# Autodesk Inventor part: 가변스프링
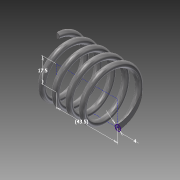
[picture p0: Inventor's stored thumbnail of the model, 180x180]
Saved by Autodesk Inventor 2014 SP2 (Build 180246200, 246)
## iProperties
Created: 2015-03
Part Number: 가변스프링
Material: 강철, 탄소
Document SubType Name: Modeling
Designer: 201-01
Density: 7.87 g/cm^3
Appearance: 반연마
Mass: 47.9796 g
Surface Area: 62.0291 cm^2
Volume: 6.09652 cm^3
Author: 201-01
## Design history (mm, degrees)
sketch "스케치2"
  geometry: L1 (0, 0)-(43.5, 0); L2 (43.5, 0)-(43.5, -17.5); L3 (43.5, -17.5)-(0, -17.5); L4 (0, -17.5)-(0, 0); C1 r 2 at (0, -17.5)
  constraints: 8 end point, 2 parallel, 1 centre point, 1 coincident, 1 horizontal, 1 perpendicular
  dimensions: "d0" = 17.5 distance of L1.end L2.end; "d1" = 43.5 distance of L2.end L3.end (derived); "d2" = 4 diameter of C1
feature "코일1" sketch "스케치2" pitch "d3" = 10; turns "d5" = 4.5; dims "d4" = 43.5 (= d1), "d6" = 0, angle "d7" = 90 deg, angle "d8" = 90 deg, "d9" = 0, "d10" = 0
sketch "스케치3"
  geometry: L1 (0, -19.5)-(0, -15.5) reference; 1 further point
  constraints: 1 vertical alignment
extrude "돌출1" cut sketch "스케치3" distance "d11" = 10; taper "d12" = 0 deg
node "작업 평면1"
sketch "스케치4"
  geometry: L1 (0, 15.5)-(0, 19.5) reference; 2 further points
  constraints: 2 other
extrude "돌출2" cut sketch "스케치4" distance "d13" = 10; taper "d14" = 0 deg
node "솔리드1"
node "절단 모서리 투영1"
node "절단 모서리 투영2"
